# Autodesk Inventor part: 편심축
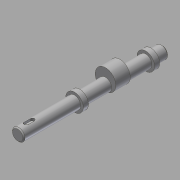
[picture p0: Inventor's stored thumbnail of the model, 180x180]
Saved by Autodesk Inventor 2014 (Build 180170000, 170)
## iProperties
Created: 2016-02
Part Number: 편심축
Material: 강철, 연강
Document SubType Name: Modeling
Designer: mduedu
Density: 1 g/cm^3
Appearance: 강철
Author: mduedu
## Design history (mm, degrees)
sketch "스케치1"
  geometry: C1 r 6 at (0, 0); 1 further point
  constraints: 1 centre point, 1 coincident
  dimensions: "d0" = 12 diameter of C1
extrude "돌출1" new body sketch "스케치1" distance "d1" = 140; taper "d2" = 0 deg
chamfer "모따기1" distance "d3" = 1; stored, may be unused: second distance "d4" = 2, angle "d5" = 45 deg
node "작업 평면1"
sketch "스케치2"
  geometry: C1 r 10 at (0, 4); C2 r 6 at (0, 0) reference; 1 further point
  constraints: 1 centre point, 1 tangent, 1 vertical alignment
  dimensions: "d7" = 20 diameter of C1
extrude "돌출2" join sketch "스케치2" stored distance "d8" = 14; taper "d9" = 0 deg
node "작업 평면2"
sketch "스케치3"
  geometry: C1 r 8.5 at (0, 0); 1 further point
  constraints: 1 centre point, 1 coincident
  dimensions: "d12" = 17 diameter of C1
extrude "돌출3" join sketch "스케치3" distance "d13" = 5; taper "d14" = 0 deg
node "작업 평면3"
sketch "스케치4"
  geometry: L1 (-5, 140)-(5, 140) reference; L2 (0, 140)-(0, 0); L3 (-2, 132)-(-2, 126); L4 (2, 126)-(2, 132); A1 r 2 centre (0, 132) between (2, 132) and (-2, 132); A2 r 2 centre (0, 126) between (-2, 126) and (2, 126)
  constraints: 6 end point, 4 point on circle, 4 tangent, 2 centre point, 2 point on line, 1 midpoint, 1 parallel, 1 perpendicular
  dimensions: "d15" = 4 distance between parallel lines of L3 L4; "d17" = 6 distance edge to line of A1 L1; "d18" = 10 dimension on A2 A1
extrude "돌출4" cut sketch "스케치4" distance "d19" = 2.5; taper "d20" = 0 deg
sketch "스케치5"
  geometry: L1 (6, 55)-(6, 139) reference; L2 (-6, 55)-(-6, 139) reference; L3 (6, 115)-(-6, 115); L4 (-5, 140)-(5, 140) reference; L5 (6, 116.5)-(4.5, 115); L6 (6, 116.5)-(6, 115); L7 (4.5, 115)-(6, 115); 1 further point
  constraints: 8 end point, 4 point on line, 2 collinear, 1 perpendicular
  dimensions: "d21" = 25 distance between parallel lines of L3 L4; "d22" = 3 diameter of L5.start L3; "d24" = 45 deg angle of L3 L5
revolve "회전1" sketch "스케치5" stored, may be unused: angle "d25" = 90 deg
sketch "스케치6"
  geometry: L1 (6, 116.5)-(4.5, 115) reference; L2 (6, 113.5)-(4.5, 115) reference; 2 further points
  constraints: 1 coincident
node "작업 평면4"
sketch "스케치7"
  geometry: C1 r 8.5 at (0, -4); 1 further point
  constraints: 1 centre point, 1 coincident
  dimensions: "d27" = 17 diameter of C1
extrude "돌출5" join sketch "스케치7" distance "d29" = 5; taper "d30" = 0 deg
node "솔리드1"
other parameters: "d6" = -48, "d11" = -11
